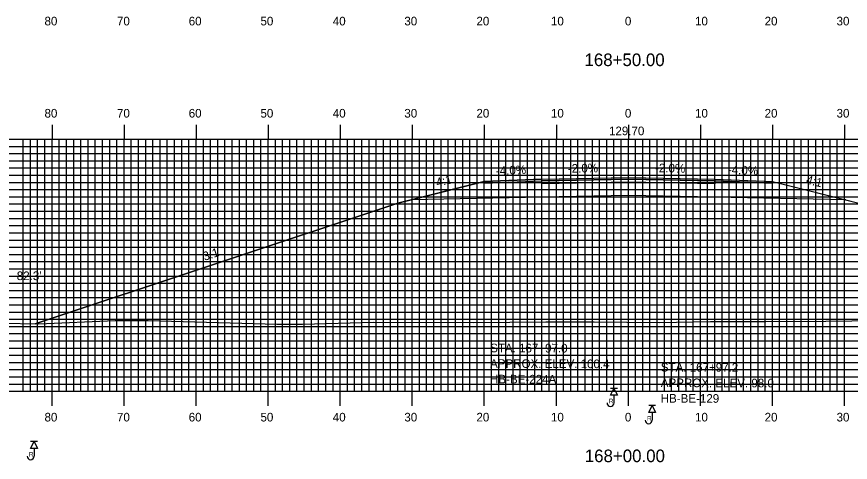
# Model space of a CAD drawing. Extents: x 1781860 to 1782203, y 442591 to 442811.
# Drawn here: x 1781941 to 1782056.7, y 442653.8 to 442715.7 of the extents above; entities that cross this region are included whole.
import ezdxf

# ---------------------------------------------------------------- set-up
doc = ezdxf.new("R2010")
doc.units = 0
for name, color, linetype in [('ANNOTATION', 7, 'Continuous'), ('BORING - REFUSAL', 7, 'Continuous'), ('D_Roadway_Centerline', 7, 'Continuous'), ('D_Roadway_Centerline_Text', 7, 'Continuous'), ('D_Roadway_Edge_Shoulder', 7, 'Continuous'), ('D_Roadway_Edge_TW', 7, 'Continuous'), ('D_Roadway_Pavement', 7, 'Continuous'), ('D_Roadway_SlopeLines', 7, 'Continuous'), ('D_Roadway_SubGrade', 7, 'Continuous'), ('D_Text_Standard', 7, 'Continuous'), ('H_V ANNOTATION', 7, 'Continuous'), ('MAJOR', 7, 'Continuous'), ('MINOR', 7, 'Continuous'), ('S_Roadway_Centerline', 7, 'Continuous')]:
    doc.layers.add(name, color=color, linetype=linetype)

msp = doc.modelspace()

# ---------------------------------------------------------------- linework, layer by layer
at = {"layer": 'BORING - REFUSAL'}
for p, q in [((1782024.4, 442664.07), (1782023.44, 442664.07)), ((1782023.92, 442663.11), (1782023.92, 442662.05)), ((1782029.7, 442661.67), (1782028.74, 442661.67)), ((1782029.22, 442660.71), (1782029.22, 442659.65)), ((1781943.9, 442656.67), (1781942.94, 442656.67)), ((1781943.42, 442655.71), (1781943.42, 442654.65))]:
    msp.add_line(p, q, dxfattribs=at)
for points in [[(1782023.92, 442664.07), (1782024.4, 442663.11), (1782023.44, 442663.11)], [(1782029.22, 442661.67), (1782029.7, 442660.71), (1782028.74, 442660.71)], [(1781943.42, 442656.67), (1781943.9, 442655.71), (1781942.94, 442655.71)]]:
    msp.add_lwpolyline(points, close=True, dxfattribs=at)
for centre in [(1782023.44, 442662.05), (1782028.74, 442659.65), (1781942.94, 442654.65)]:
    msp.add_arc(centre, 0.485, 180, 0, dxfattribs=at)
at = {"layer": 'D_Roadway_Centerline'}
msp.add_lwpolyline([(1781943.58, 442673.02), (1781993.92, 442689.8), (1781995.75, 442690.26), (1782005.92, 442692.8), (1782013.92, 442693.12), (1782025.92, 442693.36), (1782037.92, 442693.12), (1782045.92, 442692.8), (1782056.09, 442690.26), (1782057.92, 442689.8), (1782102.21, 442675.04)], dxfattribs=at)
at = {"layer": 'D_Roadway_Edge_Shoulder'}
for points in [[(1782013.92, 442693.12), (1782005.92, 442692.8), (1782005.92, 442692.55), (1782013.92, 442692.87)], [(1782037.92, 442693.12), (1782045.92, 442692.8), (1782045.92, 442692.55), (1782037.92, 442692.87)]]:
    msp.add_lwpolyline(points, close=True, dxfattribs=at)
at = {"layer": 'D_Roadway_Edge_TW'}
msp.add_lwpolyline([(1782013.92, 442692.87), (1782013.92, 442693.12), (1782025.92, 442693.36), (1782037.92, 442693.12), (1782037.92, 442692.87), (1782025.92, 442693.11)], close=True, dxfattribs=at)
at = {"layer": 'D_Roadway_Pavement'}
msp.add_lwpolyline([(1782013.92, 442692.46), (1782013.92, 442692.87), (1782025.92, 442693.11), (1782037.92, 442692.87), (1782037.92, 442692.46), (1782025.92, 442692.7)], close=True, dxfattribs=at)
at = {"layer": 'D_Roadway_SlopeLines'}
for points in [[(1782005.92, 442692.8), (1781993.92, 442689.8), (1781943.58, 442673.02)], [(1782045.92, 442692.8), (1782057.92, 442689.8), (1782102.21, 442675.04)]]:
    msp.add_lwpolyline(points, dxfattribs=at)
at = {"layer": 'D_Roadway_SubGrade'}
msp.add_lwpolyline([(1782013.92, 442690.62), (1781995.75, 442690.26), (1782005.92, 442692.8), (1782005.92, 442692.55), (1782013.92, 442692.87), (1782025.92, 442693.11), (1782037.92, 442692.87), (1782045.92, 442692.55), (1782045.92, 442692.8), (1782056.09, 442690.26), (1782037.92, 442690.62), (1782025.92, 442690.86)], close=True, dxfattribs=at)
at = {"layer": 'MAJOR'}
for p, q in [((1781945.92, 442700.67), (1781945.92, 442698.67)), ((1781955.92, 442700.67), (1781955.92, 442698.67)), ((1781965.92, 442700.67), (1781965.92, 442698.67)), ((1781975.92, 442700.67), (1781975.92, 442698.67)), ((1781985.92, 442700.67), (1781985.92, 442698.67)), ((1781995.92, 442700.67), (1781995.92, 442698.67)), ((1782005.92, 442700.67), (1782005.92, 442698.67)), ((1782015.92, 442700.67), (1782015.92, 442698.67)), ((1782025.92, 442700.67), (1782025.92, 442698.67)), ((1782035.92, 442700.67), (1782035.92, 442698.67)), ((1782045.92, 442700.67), (1782045.92, 442698.67)), ((1782055.92, 442700.67), (1782055.92, 442698.67)), ((1781885.92, 442698.67), (1782165.92, 442698.67)), ((1781885.92, 442698.67), (1782165.92, 442698.67)), ((1781945.92, 442663.67), (1781945.92, 442698.67)), ((1781955.92, 442663.67), (1781955.92, 442698.67)), ((1781965.92, 442663.67), (1781965.92, 442698.67)), ((1781975.92, 442663.67), (1781975.92, 442698.67)), ((1781985.92, 442663.67), (1781985.92, 442698.67)), ((1781995.92, 442663.67), (1781995.92, 442698.67)), ((1782005.92, 442663.67), (1782005.92, 442698.67)), ((1782015.92, 442663.67), (1782015.92, 442698.67)), ((1782025.92, 442663.67), (1782025.92, 442698.67)), ((1782035.92, 442663.67), (1782035.92, 442698.67)), ((1782045.92, 442663.67), (1782045.92, 442698.67)), ((1782055.92, 442663.67), (1782055.92, 442698.67)), ((1781885.92, 442693.67), (1782165.92, 442693.67)), ((1781885.92, 442688.67), (1782165.92, 442688.67)), ((1781885.92, 442683.67), (1782165.92, 442683.67)), ((1781885.92, 442678.67), (1782165.92, 442678.67)), ((1781885.92, 442673.67), (1782165.92, 442673.67)), ((1781885.92, 442668.67), (1782165.92, 442668.67)), ((1781885.92, 442663.67), (1782165.92, 442663.67)), ((1781885.92, 442663.67), (1782165.92, 442663.67)), ((1781945.92, 442661.66), (1781945.92, 442663.67)), ((1781955.92, 442661.66), (1781955.92, 442663.67)), ((1781965.92, 442661.66), (1781965.92, 442663.67)), ((1781975.92, 442661.66), (1781975.92, 442663.67)), ((1781985.92, 442661.66), (1781985.92, 442663.67)), ((1781995.92, 442661.66), (1781995.92, 442663.67)), ((1782005.92, 442661.66), (1782005.92, 442663.67)), ((1782015.92, 442661.66), (1782015.92, 442663.67)), ((1782025.92, 442661.66), (1782025.92, 442663.67)), ((1782035.92, 442661.66), (1782035.92, 442663.67)), ((1782045.92, 442661.66), (1782045.92, 442663.67)), ((1782055.92, 442661.66), (1782055.92, 442663.67))]:
    msp.add_line(p, q, dxfattribs=at)
at = {"layer": 'MINOR'}
for p, q in [((1781941.92, 442663.67), (1781941.92, 442698.67)), ((1781942.92, 442663.67), (1781942.92, 442698.67)), ((1781943.92, 442663.67), (1781943.92, 442698.67)), ((1781944.92, 442663.67), (1781944.92, 442698.67)), ((1781946.92, 442663.67), (1781946.92, 442698.67)), ((1781947.92, 442663.67), (1781947.92, 442698.67)), ((1781948.92, 442663.67), (1781948.92, 442698.67)), ((1781949.92, 442663.67), (1781949.92, 442698.67)), ((1781950.92, 442663.67), (1781950.92, 442698.67)), ((1781951.92, 442663.67), (1781951.92, 442698.67)), ((1781952.92, 442663.67), (1781952.92, 442698.67)), ((1781953.92, 442663.67), (1781953.92, 442698.67)), ((1781954.92, 442663.67), (1781954.92, 442698.67)), ((1781956.92, 442663.67), (1781956.92, 442698.67)), ((1781957.92, 442663.67), (1781957.92, 442698.67)), ((1781958.92, 442663.67), (1781958.92, 442698.67)), ((1781959.92, 442663.67), (1781959.92, 442698.67)), ((1781960.92, 442663.67), (1781960.92, 442698.67)), ((1781961.92, 442663.67), (1781961.92, 442698.67)), ((1781962.92, 442663.67), (1781962.92, 442698.67)), ((1781963.92, 442663.67), (1781963.92, 442698.67)), ((1781964.92, 442663.67), (1781964.92, 442698.67)), ((1781966.92, 442663.67), (1781966.92, 442698.67)), ((1781967.92, 442663.67), (1781967.92, 442698.67)), ((1781968.92, 442663.67), (1781968.92, 442698.67)), ((1781969.92, 442663.67), (1781969.92, 442698.67)), ((1781970.92, 442663.67), (1781970.92, 442698.67)), ((1781971.92, 442663.67), (1781971.92, 442698.67)), ((1781972.92, 442663.67), (1781972.92, 442698.67)), ((1781973.92, 442663.67), (1781973.92, 442698.67)), ((1781974.92, 442663.67), (1781974.92, 442698.67)), ((1781976.92, 442663.67), (1781976.92, 442698.67)), ((1781977.92, 442663.67), (1781977.92, 442698.67)), ((1781978.92, 442663.67), (1781978.92, 442698.67)), ((1781979.92, 442663.67), (1781979.92, 442698.67)), ((1781980.92, 442663.67), (1781980.92, 442698.67)), ((1781981.92, 442663.67), (1781981.92, 442698.67)), ((1781982.92, 442663.67), (1781982.92, 442698.67)), ((1781983.92, 442663.67), (1781983.92, 442698.67)), ((1781984.92, 442663.67), (1781984.92, 442698.67)), ((1781986.92, 442663.67), (1781986.92, 442698.67)), ((1781987.92, 442663.67), (1781987.92, 442698.67)), ((1781988.92, 442663.67), (1781988.92, 442698.67)), ((1781989.92, 442663.67), (1781989.92, 442698.67)), ((1781990.92, 442663.67), (1781990.92, 442698.67)), ((1781991.92, 442663.67), (1781991.92, 442698.67)), ((1781992.92, 442663.67), (1781992.92, 442698.67)), ((1781993.92, 442663.67), (1781993.92, 442698.67)), ((1781994.92, 442663.67), (1781994.92, 442698.67)), ((1781996.92, 442663.67), (1781996.92, 442698.67)), ((1781997.92, 442663.67), (1781997.92, 442698.67)), ((1781998.92, 442663.67), (1781998.92, 442698.67)), ((1781999.92, 442663.67), (1781999.92, 442698.67)), ((1782000.92, 442663.67), (1782000.92, 442698.67)), ((1782001.92, 442663.67), (1782001.92, 442698.67)), ((1782002.92, 442663.67), (1782002.92, 442698.67)), ((1782003.92, 442663.67), (1782003.92, 442698.67)), ((1782004.92, 442663.67), (1782004.92, 442698.67)), ((1782006.92, 442663.67), (1782006.92, 442698.67)), ((1782007.92, 442663.67), (1782007.92, 442698.67)), ((1782008.92, 442663.67), (1782008.92, 442698.67)), ((1782009.92, 442663.67), (1782009.92, 442698.67)), ((1782010.92, 442663.67), (1782010.92, 442698.67)), ((1782011.92, 442663.67), (1782011.92, 442698.67)), ((1782012.92, 442663.67), (1782012.92, 442698.67)), ((1782013.92, 442663.67), (1782013.92, 442698.67)), ((1782014.92, 442663.67), (1782014.92, 442698.67)), ((1782016.92, 442663.67), (1782016.92, 442698.67)), ((1782017.92, 442663.67), (1782017.92, 442698.67)), ((1782018.92, 442663.67), (1782018.92, 442698.67)), ((1782019.92, 442663.67), (1782019.92, 442698.67)), ((1782020.92, 442663.67), (1782020.92, 442698.67)), ((1782021.92, 442663.67), (1782021.92, 442698.67)), ((1782022.92, 442663.67), (1782022.92, 442698.67)), ((1782023.92, 442663.67), (1782023.92, 442698.67)), ((1782024.92, 442663.67), (1782024.92, 442698.67)), ((1782026.92, 442663.67), (1782026.92, 442698.67)), ((1782027.92, 442663.67), (1782027.92, 442698.67)), ((1782028.92, 442663.67), (1782028.92, 442698.67)), ((1782029.92, 442663.67), (1782029.92, 442698.67)), ((1782030.92, 442663.67), (1782030.92, 442698.67)), ((1782031.92, 442663.67), (1782031.92, 442698.67)), ((1782032.92, 442663.67), (1782032.92, 442698.67)), ((1782033.92, 442663.67), (1782033.92, 442698.67)), ((1782034.92, 442663.67), (1782034.92, 442698.67)), ((1782036.92, 442663.67), (1782036.92, 442698.67)), ((1782037.92, 442663.67), (1782037.92, 442698.67)), ((1782038.92, 442663.67), (1782038.92, 442698.67)), ((1782039.92, 442663.67), (1782039.92, 442698.67)), ((1782040.92, 442663.67), (1782040.92, 442698.67)), ((1782041.92, 442663.67), (1782041.92, 442698.67)), ((1782042.92, 442663.67), (1782042.92, 442698.67)), ((1782043.92, 442663.67), (1782043.92, 442698.67)), ((1782044.92, 442663.67), (1782044.92, 442698.67)), ((1782046.92, 442663.67), (1782046.92, 442698.67)), ((1782047.92, 442663.67), (1782047.92, 442698.67)), ((1782048.92, 442663.67), (1782048.92, 442698.67)), ((1782049.92, 442663.67), (1782049.92, 442698.67)), ((1782050.92, 442663.67), (1782050.92, 442698.67)), ((1782051.92, 442663.67), (1782051.92, 442698.67)), ((1782052.92, 442663.67), (1782052.92, 442698.67)), ((1782053.92, 442663.67), (1782053.92, 442698.67)), ((1782054.92, 442663.67), (1782054.92, 442698.67)), ((1781885.92, 442697.67), (1782165.92, 442697.67)), ((1781885.92, 442696.67), (1782165.92, 442696.67)), ((1781885.92, 442695.67), (1782165.92, 442695.67)), ((1781885.92, 442694.67), (1782165.92, 442694.67)), ((1781885.92, 442692.67), (1782165.92, 442692.67)), ((1781885.92, 442691.67), (1782165.92, 442691.67)), ((1781885.92, 442690.67), (1782165.92, 442690.67)), ((1781885.92, 442689.67), (1782165.92, 442689.67)), ((1781885.92, 442687.67), (1782165.92, 442687.67)), ((1781885.92, 442686.67), (1782165.92, 442686.67)), ((1781885.92, 442685.67), (1782165.92, 442685.67)), ((1781885.92, 442684.67), (1782165.92, 442684.67)), ((1781885.92, 442682.67), (1782165.92, 442682.67)), ((1781885.92, 442681.67), (1782165.92, 442681.67)), ((1781885.92, 442680.67), (1782165.92, 442680.67)), ((1781885.92, 442679.67), (1782165.92, 442679.67)), ((1781885.92, 442677.67), (1782165.92, 442677.67)), ((1781885.92, 442676.67), (1782165.92, 442676.67)), ((1781885.92, 442675.67), (1782165.92, 442675.67)), ((1781885.92, 442674.67), (1782165.92, 442674.67)), ((1781885.92, 442672.67), (1782165.92, 442672.67)), ((1781885.92, 442671.67), (1782165.92, 442671.67)), ((1781885.92, 442670.67), (1782165.92, 442670.67)), ((1781885.92, 442669.67), (1782165.92, 442669.67)), ((1781885.92, 442667.67), (1782165.92, 442667.67)), ((1781885.92, 442666.67), (1782165.92, 442666.67)), ((1781885.92, 442665.67), (1782165.92, 442665.67)), ((1781885.92, 442664.67), (1782165.92, 442664.67))]:
    msp.add_line(p, q, dxfattribs=at)
at = {"layer": 'S_Roadway_Centerline'}
msp.add_lwpolyline([(1781885.92, 442673.53), (1781886.64, 442673.52), (1781897.56, 442673.61), (1781908.41, 442673.34), (1781909, 442673.33), (1781909.59, 442673.32), (1781921.1, 442673.18), (1781930.79, 442673.23), (1781933.76, 442673.2), (1781944.09, 442673.01), (1781954.67, 442673.47), (1781959.27, 442673.5), (1781977.13, 442673), (1781980.69, 442672.98), (1781990.57, 442673.26), (1782004.47, 442673.22), (1782014.46, 442673.3), (1782021.16, 442673.31), (1782025.72, 442673.25), (1782030.25, 442673.23), (1782037.34, 442673.36), (1782045, 442673.37), (1782053.31, 442673.39), (1782060.57, 442673.51)], dxfattribs=at)

# ---------------------------------------------------------------- texts
at = {"layer": 'ANNOTATION'}
for s, rotation, p in [('-4.0%', 2.2906, (1782007.55, 442693.67)), ('-2.0%', 1.1458, (1782017.53, 442694)), ('-2.0%', 358.8542, (1782029.61, 442694.09)), ('-4.0%', 357.7094, (1782039.71, 442693.85)), ('4:1', 14.0362, (1781999.37, 442692.03)), ('4:1', 345.9638, (1782050.51, 442692.52)), ('3:1', 18.4348, (1781967.09, 442681.77))]:
    msp.add_text(s, height=1.2, rotation=rotation, dxfattribs=at).set_placement(p)
at = {"layer": 'BORING - REFUSAL'}
for s, p in [('STA. 167+97.0', (1782006.73, 442669.08)), ('APPROX. ELEV. 100.4', (1782006.72, 442666.92)), ('STA. 167+97.2', (1782030.42, 442666.41)), ('HB-BE-224A', (1782006.72, 442664.76)), ('APPROX. ELEV. 98.0', (1782030.42, 442664.25)), ('HB-BE-129', (1782030.41, 442662.09))]:
    msp.add_text(s, height=1.2, rotation=359.8142, dxfattribs=at).set_placement(p)
for p in [(1782023.21, 442661.99), (1782028.51, 442659.59), (1781942.71, 442654.59)]:
    msp.add_text('R', height=0.64, dxfattribs=at).set_placement(p)
at = {"layer": 'D_Roadway_Centerline'}
for s in ['C', 'L']:
    msp.add_text(s, height=0.0146, dxfattribs=at).set_placement((1782025.92, 442693.36))
at = {"layer": 'D_Roadway_Centerline_Text'}
msp.add_text('129.70', height=1.2, dxfattribs=at).set_placement((1782023.23, 442699.22))
at = {"layer": 'D_Text_Standard'}
msp.add_text("82.3'", height=1.2, dxfattribs=at).set_placement((1781941.02, 442679.1))
at = {"layer": 'H_V ANNOTATION'}
for s, height, p in [('80', 1.2, (1781944.87, 442714.47)), ('70', 1.2, (1781954.93, 442714.47)), ('60', 1.2, (1781964.89, 442714.47)), ('50', 1.2, (1781974.85, 442714.47)), ('40', 1.2, (1781984.89, 442714.47)), ('30', 1.2, (1781994.82, 442714.47)), ('20', 1.2, (1782004.83, 442714.47)), ('10', 1.2, (1782015.17, 442714.47)), ('0', 1.2, (1782025.44, 442714.47)), ('10', 1.2, (1782035.17, 442714.47)), ('20', 1.2, (1782044.83, 442714.47)), ('30', 1.2, (1782054.82, 442714.47)), ('168+50.00', 1.75, (1782019.83, 442708.82)), ('80', 1.2, (1781944.87, 442701.67)), ('70', 1.2, (1781954.93, 442701.67)), ('60', 1.2, (1781964.89, 442701.67)), ('50', 1.2, (1781974.85, 442701.67)), ('40', 1.2, (1781984.89, 442701.67)), ('30', 1.2, (1781994.82, 442701.67)), ('20', 1.2, (1782004.83, 442701.67)), ('10', 1.2, (1782015.17, 442701.67)), ('0', 1.2, (1782025.44, 442701.67)), ('10', 1.2, (1782035.17, 442701.67)), ('20', 1.2, (1782044.83, 442701.67)), ('30', 1.2, (1782054.82, 442701.67)), ('80', 1.2, (1781944.87, 442659.47)), ('70', 1.2, (1781954.93, 442659.47)), ('60', 1.2, (1781964.89, 442659.47)), ('50', 1.2, (1781974.85, 442659.47)), ('40', 1.2, (1781984.89, 442659.47)), ('30', 1.2, (1781994.82, 442659.47)), ('20', 1.2, (1782004.83, 442659.47)), ('10', 1.2, (1782015.17, 442659.47)), ('0', 1.2, (1782025.44, 442659.47)), ('10', 1.2, (1782035.17, 442659.47)), ('20', 1.2, (1782044.83, 442659.47)), ('30', 1.2, (1782054.82, 442659.47)), ('168+00.00', 1.75, (1782019.87, 442653.82))]:
    msp.add_text(s, height=height, dxfattribs=at).set_placement(p)

doc.saveas('drawing.dxf')
